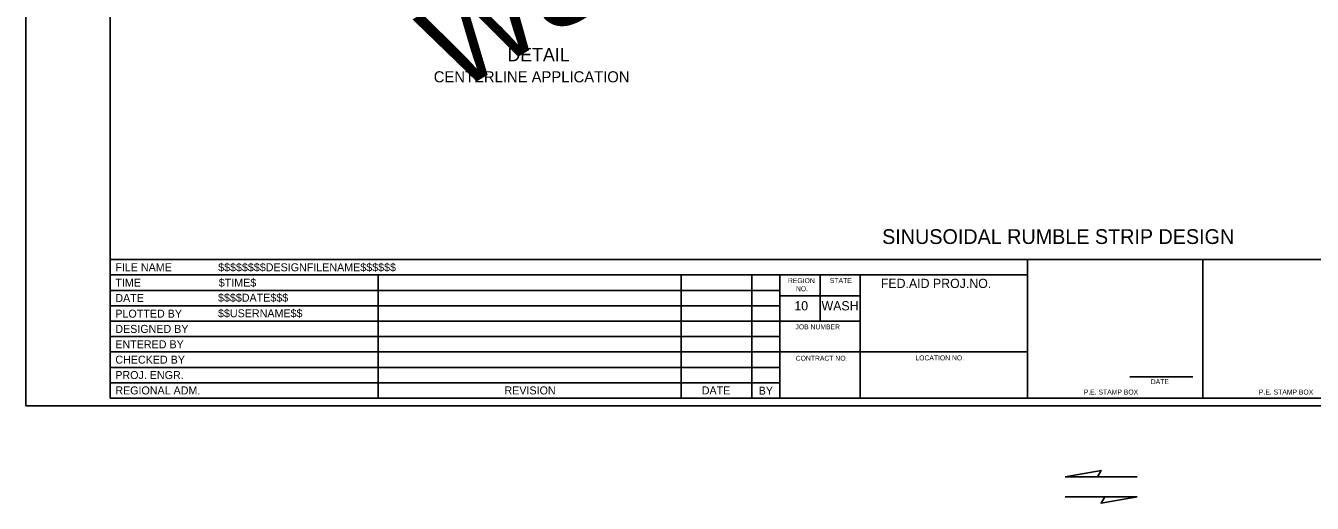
# Model space of a CAD drawing. Extents: x 100019.3 to 100035.8, y 99999.9 to 100024.4.
# Drawn here: x 100019.31 to 100029.77, y 100013.15 to 100017.03 of the extents above; entities that cross this region are included whole.
import ezdxf

# ---------------------------------------------------------------- set-up
doc = ezdxf.new("R2010")
doc.units = 0
for name, color, linetype in [('Level 16', 7, 'Continuous'), ('Level 20', 7, 'Continuous'), ('SH_GI_PlotLimits', 7, 'Continuous'), ('SH_GI_SheetBorder', 7, 'Continuous'), ('SH_GI_SheetTextInCells', 7, 'Continuous'), ('SH_GI_TitleBlockText', 7, 'Continuous'), ('SH_GI_TrafficMvmntArrowRt1Lane', 7, 'Continuous')]:
    doc.layers.add(name, color=color, linetype=linetype)

msp = doc.modelspace()

# ---------------------------------------------------------------- linework, layer by layer
at = {"layer": 'SH_GI_PlotLimits'}
msp.add_lwpolyline([(100019.312, 100013.937), (100035.812, 100013.937), (100035.812, 100024.437), (100019.312, 100024.437)], close=True, dxfattribs=at)
at = {"layer": 'SH_GI_SheetBorder'}
for p, q in [((100020, 100024.375), (100020, 100014)), ((100020, 100015.126), (100035.75, 100015.126)), ((100027.457, 100014), (100027.457, 100015.126)), ((100028.883, 100014), (100028.883, 100015.126)), ((100020, 100015.001), (100027.457, 100015.001)), ((100022.179, 100015.001), (100022.179, 100014)), ((100024.641, 100015.001), (100024.641, 100014)), ((100025.216, 100015.001), (100025.216, 100014)), ((100025.445, 100015.001), (100025.445, 100014)), ((100025.772, 100014.625), (100025.772, 100015.001)), ((100026.096, 100014), (100026.096, 100015.001)), ((100020, 100014.876), (100022.182, 100014.876)), ((100022.182, 100014.876), (100025.447, 100014.876)), ((100026.096, 100014.831), (100025.447, 100014.831)), ((100020, 100014.751), (100022.182, 100014.751)), ((100022.182, 100014.751), (100025.447, 100014.751)), ((100020, 100014.625), (100025.447, 100014.625)), ((100026.096, 100014.625), (100025.447, 100014.625)), ((100020, 100014.5), (100025.447, 100014.5)), ((100020, 100014.375), (100025.447, 100014.375)), ((100027.457, 100014.375), (100025.447, 100014.375)), ((100020, 100014.25), (100025.447, 100014.25)), ((100028.29, 100014.173), (100028.802, 100014.173)), ((100020, 100014.125), (100025.447, 100014.125)), ((100020, 100014), (100035.75, 100014))]:
    msp.add_line(p, q, dxfattribs=at)
at = {"layer": 'SH_GI_TrafficMvmntArrowRt1Lane'}
for p, q in [((100028.026, 100013.361), (100028.348, 100013.361)), ((100028.086, 100013.197), (100027.764, 100013.197))]:
    msp.add_line(p, q, dxfattribs=at)
for points in [[(100027.764, 100013.361), (100028.056, 100013.412), (100028.026, 100013.361)], [(100028.348, 100013.197), (100028.056, 100013.145), (100028.086, 100013.197)]]:
    msp.add_lwpolyline(points, close=True, dxfattribs=at)

# ---------------------------------------------------------------- texts
at = {"layer": 'Level 16'}
msp.add_text('WSDOT HQ Design Office', height=0.7, rotation=30.7778, dxfattribs=at).set_placement((100022.812, 100016.475))
at = {"layer": 'Level 20'}
for s, height, p in [('DETAIL', 0.108, (100023.229, 100016.738)), ('CENTERLINE APPLICATION', 0.09, (100022.63, 100016.567)), ('SINUSOIDAL RUMBLE STRIP DESIGN', 0.12, (100026.276, 100015.253))]:
    msp.add_text(s, height=height, dxfattribs=at).set_placement(p)
at = {"layer": 'SH_GI_SheetTextInCells'}
for s, height, p in [('FILE NAME', 0.0651, (100020.041, 100015.031)), ('TIME', 0.0651, (100020.041, 100014.906)), ('REGION', 0.04, (100025.51, 100014.935)), ('NO.', 0.04, (100025.575, 100014.869)), ('STATE', 0.04, (100025.851, 100014.936)), ('FED.AID PROJ.NO.', 0.07506, (100026.265, 100014.895)), ('DATE', 0.0651, (100020.041, 100014.781)), ('PLOTTED BY', 0.0651, (100020.041, 100014.654)), ('10', 0.0751, (100025.562, 100014.713)), ('WASH', 0.0751, (100025.783, 100014.713)), ('DESIGNED BY', 0.06505, (100020.041, 100014.53)), ('JOB NUMBER', 0.04, (100025.571, 100014.559)), ('ENTERED BY', 0.0651, (100020.041, 100014.405)), ('CHECKED BY', 0.0651, (100020.041, 100014.28)), ('CONTRACT NO.', 0.04003, (100025.573, 100014.304)), ('LOCATION NO.', 0.04003, (100026.546, 100014.307)), ('PROJ. ENGR.', 0.06505, (100020.041, 100014.155)), ('REGIONAL ADM.', 0.06505, (100020.041, 100014.03)), ('REVISION', 0.0651, (100023.205, 100014.03)), ('DATE', 0.0651, (100024.809, 100014.03)), ('BY', 0.0651, (100025.272, 100014.028)), ('P.E. STAMP BOX', 0.04003, (100027.915, 100014.029)), ('DATE', 0.04, (100028.46, 100014.114)), ('P.E. STAMP BOX', 0.04003, (100029.339, 100014.029))]:
    msp.add_text(s, height=height, dxfattribs=at).set_placement(p)
at = {"layer": 'SH_GI_TitleBlockText'}
for s, height, p in [('$$$$$$$$DESIGNFILENAME$$$$$$', 0.06505, (100020.877, 100015.031)), ('$TIME$', 0.0651, (100020.882, 100014.906)), ('$$$$DATE$$$', 0.06505, (100020.876, 100014.784)), ('$$USERNAME$$', 0.06505, (100020.876, 100014.657))]:
    msp.add_text(s, height=height, dxfattribs=at).set_placement(p)

doc.saveas('drawing.dxf')
